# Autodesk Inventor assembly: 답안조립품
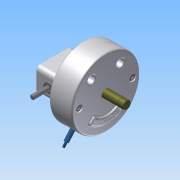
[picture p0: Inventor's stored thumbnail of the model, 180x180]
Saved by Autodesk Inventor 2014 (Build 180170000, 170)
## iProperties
Created: 2015-04
Part Number: 답안조립품
Document SubType Name: Assembly
Designer: Administrator
Author: Administrator
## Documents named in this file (15)
- C:\Documents and Settings\Administrator\바탕 화면\350406V1030\답안조립품.iam
- C:\Documents and Settings\Administrator\바탕 화면\350406V1030\본체.ipt
- C:\Documents and Settings\Administrator\바탕 화면\350406V1030\커버2.ipt
- C:\Documents and Settings\Administrator\바탕 화면\350406V1030\M 5 x 12.ipt
- C:\Documents and Settings\Administrator\바탕 화면\350406V1030\축.ipt
- C:\Documents and Settings\Administrator\바탕 화면\350406V1030\멈춤링.ipt
- C:\Documents and Settings\Administrator\바탕 화면\350406V1030\베어링62_22.ipt
- C:\Documents and Settings\Administrator\바탕 화면\350406V1030\슬라이더2.ipt
- C:\Documents and Settings\Administrator\바탕 화면\350406V1030\슬라이더.ipt
- C:\Documents and Settings\Administrator\바탕 화면\350406V1030\평행핀.ipt
- C:\Documents and Settings\Administrator\바탕 화면\350406V1030\슬라이더3.ipt
- C:\Documents and Settings\Administrator\바탕 화면\350406V1030\부시.ipt
- C:\Documents and Settings\Administrator\바탕 화면\350406V1030\스프링 - [가변].ipt
- C:\Documents and Settings\Administrator\바탕 화면\350406V1030\커버.ipt
- C:\Documents and Settings\Administrator\바탕 화면\350406V1030\M 10 x 35.ipt
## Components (5 placed, 3 different names)
1. M 5 x 12:1
2. M 5 x 12:2
3. KS B 1320 B B 5 x  20:1 — 플러쉬:1
4. M 10 x 35:1
5. M 10 x 35:2
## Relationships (1: Flush 1)
- 플러쉬:1 [Flush]: KS B 1320 B B 5 x  20:1
